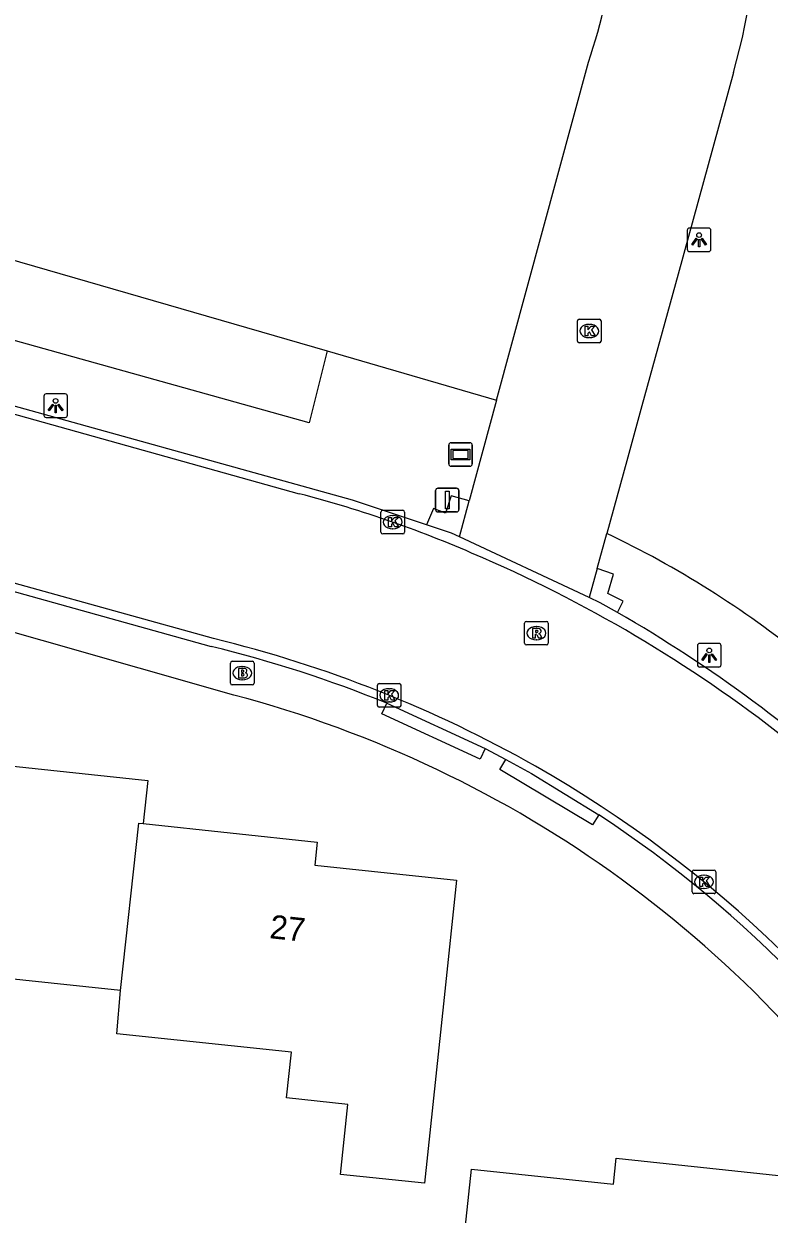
# Model space of a CAD drawing. Extents: x 162157 to 163165, y 378998 to 380775.
# Drawn here: x 162604.1 to 162635.7, y 380579.8 to 380630.1 of the extents above; entities that cross this region are included whole.
import ezdxf

# ---------------------------------------------------------------- set-up
doc = ezdxf.new("R2010")
doc.units = 0
for name, color, linetype in [('IMGEO_Afsluitpaal', 7, 'Continuous'), ('IMGEO_Berm_groen', 7, 'Continuous'), ('IMGEO_Brandkraan', 7, 'Continuous'), ('IMGEO_Groenvoorziening', 7, 'Continuous'), ('IMGEO_Kolk', 7, 'Continuous'), ('IMGEO_Lichtpunt', 7, 'Continuous'), ('IMGEO_Pand', 7, 'Continuous'), ('IMGEO_Pand_nummerreeks', 7, 'Continuous'), ('IMGEO_Rijbaan_lokaal_gesloten', 7, 'Continuous'), ('IMGEO_Rijbaan_lokaal_open', 7, 'Continuous'), ('IMGEO_Rioolput', 7, 'Continuous'), ('IMGEO_Verklikker', 7, 'Continuous'), ('IMGEO_Voetpad_open', 7, 'Continuous')]:
    doc.layers.add(name, color=color, linetype=linetype)

msp = doc.modelspace()

# ---------------------------------------------------------------- linework, layer by layer
at = {"layer": 'IMGEO_Afsluitpaal'}
for p, q in [((162621.56, 380609.58), (162621.56, 380610.38)), ((162621.56, 380610.38), (162621.56, 380609.58)), ((162621.66, 380610.48), (162622.45, 380610.48)), ((162622.45, 380610.48), (162621.66, 380610.48)), ((162622.55, 380610.38), (162622.55, 380609.58)), ((162622.55, 380609.58), (162622.55, 380610.38)), ((162622.45, 380609.48), (162621.66, 380609.48)), ((162621.66, 380609.48), (162622.45, 380609.48))]:
    msp.add_line(p, q, dxfattribs=at)
msp.add_lwpolyline([(162621.98, 380610.355), (162622.13, 380610.355), (162622.13, 380609.605), (162621.98, 380609.605), (162621.98, 380610.355)], dxfattribs=at)
for centre, start, end in [((162621.66, 380610.38), 90, 180), ((162621.66, 380610.38), 90, 180), ((162622.45, 380610.38), 0, 90), ((162622.45, 380610.38), 360, 90), ((162621.66, 380609.58), 180, 270), ((162621.66, 380609.58), 180, 270), ((162622.45, 380609.58), 270, 0), ((162622.45, 380609.58), 270, 0)]:
    msp.add_arc(centre, 0.1, start, end, dxfattribs=at)
at = {"layer": 'IMGEO_Berm_groen'}
for points in [[(162616.972, 380616.299), (162616.207, 380613.255), (162569.302, 380626.35)], [(162616.972, 380616.299), (162624.141, 380614.215)]]:
    msp.add_lwpolyline(points, dxfattribs=at)
msp.add_arc((162610.535, 380570.327), 42.385, 51.0619, 64.4657, dxfattribs=at)
at = {"layer": 'IMGEO_Brandkraan'}
for p, q in [((162612.951, 380603.158), (162613.803, 380603.158)), ((162612.876, 380602.232), (162612.876, 380603.084)), ((162613.364, 380602.938), (162613.389, 380602.938)), ((162613.877, 380603.084), (162613.877, 380602.232)), ((162613.803, 380602.158), (162612.951, 380602.158)), ((162613.387, 380602.378), (162613.362, 380602.378))]:
    msp.add_line(p, q, dxfattribs=at)
for points in [[(162612.951, 380603.158), (162613.803, 380603.158)], [(162612.876, 380602.232), (162612.876, 380603.084)], [(162613.224, 380602.858), (162613.224, 380602.458), (162613.437, 380602.458)], [(162613.455, 380602.858), (162613.224, 380602.858)], [(162613.403, 380602.777), (162613.349, 380602.777), (162613.349, 380602.701)], [(162613.349, 380602.701), (162613.402, 380602.701)], [(162613.877, 380603.084), (162613.877, 380602.232)], [(162613.803, 380602.158), (162612.951, 380602.158)], [(162613.411, 380602.625), (162613.349, 380602.625), (162613.349, 380602.544)], [(162613.349, 380602.544), (162613.411, 380602.544)]]:
    msp.add_lwpolyline(points, dxfattribs=at)
for centre, radius, start, end in [((162612.953, 380603.082), 0.0765, 91.552, 178.448), ((162612.953, 380603.082), 0.0765, 91.552, 178.448), ((162613.801, 380603.082), 0.0765, 1.552, 88.448), ((162613.801, 380603.082), 0.0765, 1.552, 88.448), ((162613.404, 380602.739), 0.0379, 267.8285, 90.9355), ((162613.459, 380602.713), 0.145, 59.4692, 91.5367), ((162613.484, 380602.76), 0.0922, 285.5137, 58.1501), ((162613.489, 380602.568), 0.105, 301.3115, 78.989), ((162612.953, 380602.234), 0.0765, 181.552, 268.448), ((162612.953, 380602.234), 0.0765, 181.552, 268.448), ((162613.412, 380602.584), 0.0404, 269.8759, 90.5077), ((162613.443, 380602.709), 0.251, 268.6676, 293.5347), ((162613.801, 380602.234), 0.0765, 271.552, 358.448), ((162613.801, 380602.234), 0.0765, 271.552, 358.448)]:
    msp.add_arc(centre, radius, start, end, dxfattribs=at)
for centre, major_axis, ratio, start_param, end_param in [((162613.363, 380602.658), (-0.387, 0.002), 0.722429, 4.712389, 7.853982), ((162613.388, 380602.658), (-0.39, 0.002), 0.717154, 1.570796, 4.712389)]:
    msp.add_ellipse(centre, major_axis=major_axis, ratio=ratio, start_param=start_param, end_param=end_param, dxfattribs=at)
at = {"layer": 'IMGEO_Groenvoorziening'}
msp.add_lwpolyline([(162569.302, 380626.35), (162569.74, 380629.441), (162587.591, 380624.791), (162616.972, 380616.299)], dxfattribs=at)
at = {"layer": 'IMGEO_Kolk'}
for p, q in [((162627.566, 380616.712), (162627.566, 380617.564)), ((162627.641, 380617.638), (162628.493, 380617.638)), ((162628.054, 380617.418), (162628.079, 380617.418)), ((162628.567, 380617.564), (162628.567, 380616.712)), ((162628.077, 380616.858), (162628.052, 380616.858)), ((162628.493, 380616.638), (162627.641, 380616.638)), ((162619.246, 380608.622), (162619.246, 380609.474)), ((162619.321, 380609.548), (162620.173, 380609.548)), ((162619.734, 380609.328), (162619.759, 380609.328)), ((162620.247, 380609.474), (162620.247, 380608.622)), ((162619.757, 380608.768), (162619.732, 380608.768)), ((162620.173, 380608.548), (162619.321, 380608.548)), ((162619.095, 380601.29), (162619.095, 380602.142)), ((162619.17, 380602.216), (162620.022, 380602.216)), ((162620.096, 380602.142), (162620.096, 380601.29)), ((162619.583, 380601.996), (162619.608, 380601.996)), ((162620.022, 380601.216), (162619.17, 380601.216)), ((162619.606, 380601.436), (162619.581, 380601.436)), ((162632.422, 380593.394), (162632.422, 380594.246)), ((162632.497, 380594.32), (162633.349, 380594.32)), ((162632.91, 380594.1), (162632.935, 380594.1)), ((162633.423, 380594.246), (162633.423, 380593.394)), ((162633.349, 380593.32), (162632.497, 380593.32)), ((162632.933, 380593.54), (162632.908, 380593.54))]:
    msp.add_line(p, q, dxfattribs=at)
for points in [[(162627.566, 380616.712), (162627.566, 380617.564)], [(162627.641, 380617.638), (162628.493, 380617.638)], [(162627.887, 380617.338), (162628.01, 380617.338), (162628.01, 380617.187), (162628.14, 380617.338), (162628.304, 380617.338), (162628.158, 380617.187), (162628.311, 380616.938), (162628.159, 380616.938), (162628.074, 380617.102), (162628.01, 380617.035), (162628.01, 380616.938), (162627.887, 380616.938), (162627.887, 380617.338)], [(162628.567, 380617.564), (162628.567, 380616.712)], [(162628.493, 380616.638), (162627.641, 380616.638)], [(162619.246, 380608.622), (162619.246, 380609.474)], [(162619.321, 380609.548), (162620.173, 380609.548)], [(162619.567, 380609.248), (162619.69, 380609.248), (162619.69, 380609.097), (162619.82, 380609.248), (162619.984, 380609.248), (162619.838, 380609.097), (162619.991, 380608.848), (162619.839, 380608.848), (162619.754, 380609.012), (162619.69, 380608.945), (162619.69, 380608.848), (162619.567, 380608.848), (162619.567, 380609.248)], [(162620.247, 380609.474), (162620.247, 380608.622)], [(162620.173, 380608.548), (162619.321, 380608.548)], [(162619.095, 380601.29), (162619.095, 380602.142)], [(162619.17, 380602.216), (162620.022, 380602.216)], [(162620.096, 380602.142), (162620.096, 380601.29)], [(162619.416, 380601.916), (162619.539, 380601.916), (162619.539, 380601.765), (162619.669, 380601.916), (162619.833, 380601.916), (162619.687, 380601.765), (162619.84, 380601.516), (162619.688, 380601.516), (162619.603, 380601.68), (162619.539, 380601.613), (162619.539, 380601.516), (162619.416, 380601.516), (162619.416, 380601.916)], [(162620.022, 380601.216), (162619.17, 380601.216)], [(162632.422, 380593.394), (162632.422, 380594.246)], [(162632.497, 380594.32), (162633.349, 380594.32)], [(162633.423, 380594.246), (162633.423, 380593.394)], [(162632.743, 380594.02), (162632.866, 380594.02), (162632.866, 380593.869), (162632.996, 380594.02), (162633.16, 380594.02), (162633.014, 380593.869), (162633.167, 380593.62), (162633.015, 380593.62), (162632.93, 380593.784), (162632.866, 380593.717), (162632.866, 380593.62), (162632.743, 380593.62), (162632.743, 380594.02)], [(162633.349, 380593.32), (162632.497, 380593.32)]]:
    msp.add_lwpolyline(points, dxfattribs=at)
for centre, start, end in [((162627.643, 380617.562), 91.552, 178.448), ((162627.643, 380617.562), 91.552, 178.448), ((162628.491, 380617.562), 1.552, 88.448), ((162628.491, 380617.562), 1.552, 88.448), ((162627.643, 380616.714), 181.552, 268.448), ((162627.643, 380616.714), 181.552, 268.448), ((162628.491, 380616.714), 271.552, 358.448), ((162628.491, 380616.714), 271.552, 358.448), ((162619.323, 380609.472), 91.552, 178.448), ((162619.323, 380609.472), 91.552, 178.448), ((162620.171, 380609.472), 1.552, 88.448), ((162620.171, 380609.472), 1.552, 88.448), ((162619.323, 380608.624), 181.552, 268.448), ((162619.323, 380608.624), 181.552, 268.448), ((162620.171, 380608.624), 271.552, 358.448), ((162620.171, 380608.624), 271.552, 358.448), ((162619.172, 380602.14), 91.552, 178.448), ((162619.172, 380602.14), 91.552, 178.448), ((162620.02, 380602.14), 1.552, 88.448), ((162620.02, 380602.14), 1.552, 88.448), ((162619.172, 380601.292), 181.552, 268.448), ((162619.172, 380601.292), 181.552, 268.448), ((162620.02, 380601.292), 271.552, 358.448), ((162620.02, 380601.292), 271.552, 358.448), ((162632.499, 380594.244), 91.552, 178.448), ((162632.499, 380594.244), 91.552, 178.448), ((162633.347, 380594.244), 1.552, 88.448), ((162633.347, 380594.244), 1.552, 88.448), ((162632.499, 380593.396), 181.552, 268.448), ((162632.499, 380593.396), 181.552, 268.448), ((162633.347, 380593.396), 271.552, 358.448), ((162633.347, 380593.396), 271.552, 358.448)]:
    msp.add_arc(centre, 0.0765, start, end, dxfattribs=at)
for centre, major_axis, ratio, start_param, end_param in [((162628.053, 380617.138), (-0.387, 0.002), 0.722429, 4.712389, 7.853982), ((162628.078, 380617.138), (-0.39, 0.002), 0.717154, 1.570796, 4.712389), ((162619.733, 380609.048), (-0.387, 0.002), 0.722429, 4.712389, 7.853982), ((162619.758, 380609.048), (-0.39, 0.002), 0.717154, 1.570796, 4.712389), ((162619.582, 380601.716), (-0.387, 0.002), 0.722429, 4.712389, 7.853982), ((162619.607, 380601.716), (-0.39, 0.002), 0.717154, 1.570796, 4.712389), ((162632.909, 380593.82), (-0.387, 0.002), 0.722429, 4.712389, 7.853982), ((162632.934, 380593.82), (-0.39, 0.002), 0.717154, 1.570796, 4.712389)]:
    msp.add_ellipse(centre, major_axis=major_axis, ratio=ratio, start_param=start_param, end_param=end_param, dxfattribs=at)
at = {"layer": 'IMGEO_Lichtpunt'}
for p, q in [((162632.217, 380621.402), (162632.217, 380620.595)), ((162632.217, 380621.402), (162632.217, 380620.595)), ((162633.119, 380621.497), (162632.311, 380621.497)), ((162633.119, 380621.497), (162632.311, 380621.497)), ((162633.213, 380620.595), (162633.213, 380621.402)), ((162633.213, 380620.595), (162633.213, 380621.402)), ((162632.311, 380620.501), (162633.119, 380620.501)), ((162632.311, 380620.501), (162633.119, 380620.501)), ((162604.977, 380614.383), (162604.977, 380613.576)), ((162604.977, 380614.383), (162604.977, 380613.576)), ((162605.879, 380614.478), (162605.071, 380614.478)), ((162605.879, 380614.478), (162605.071, 380614.478)), ((162605.973, 380613.576), (162605.973, 380614.383)), ((162605.973, 380613.576), (162605.973, 380614.383)), ((162605.071, 380613.482), (162605.879, 380613.482)), ((162605.071, 380613.482), (162605.879, 380613.482)), ((162632.647, 380603.816), (162632.647, 380603.009)), ((162632.647, 380603.816), (162632.647, 380603.009)), ((162633.549, 380603.911), (162632.741, 380603.911)), ((162633.549, 380603.911), (162632.741, 380603.911)), ((162633.643, 380603.009), (162633.643, 380603.816)), ((162633.643, 380603.009), (162633.643, 380603.816)), ((162632.741, 380602.915), (162633.549, 380602.915)), ((162632.741, 380602.915), (162633.549, 380602.915))]:
    msp.add_line(p, q, dxfattribs=at)
for points in [[(162632.591, 380621.066), (162632.63, 380621.038), (162632.442, 380620.776), (162632.404, 380620.803), (162632.591, 380621.066)], [(162632.693, 380621.018), (162632.74, 380621.018), (162632.74, 380620.696), (162632.693, 380620.696), (162632.693, 380621.018)], [(162632.803, 380621.038), (162632.841, 380621.065), (162633.028, 380620.803), (162632.989, 380620.775), (162632.803, 380621.038)], [(162605.351, 380614.047), (162605.39, 380614.019), (162605.202, 380613.757), (162605.164, 380613.784), (162605.351, 380614.047)], [(162605.453, 380613.999), (162605.5, 380613.999), (162605.5, 380613.677), (162605.453, 380613.677), (162605.453, 380613.999)], [(162605.563, 380614.019), (162605.601, 380614.046), (162605.788, 380613.784), (162605.749, 380613.756), (162605.563, 380614.019)], [(162633.021, 380603.48), (162633.06, 380603.452), (162632.872, 380603.19), (162632.834, 380603.217), (162633.021, 380603.48)], [(162633.123, 380603.432), (162633.17, 380603.432), (162633.17, 380603.11), (162633.123, 380603.11), (162633.123, 380603.432)], [(162633.233, 380603.452), (162633.271, 380603.479), (162633.458, 380603.217), (162633.419, 380603.189), (162633.233, 380603.452)]]:
    msp.add_lwpolyline(points, dxfattribs=at)
for centre in [(162632.716, 380621.2), (162605.476, 380614.181), (162633.146, 380603.614)]:
    msp.add_circle(centre, 0.0994, dxfattribs=at)
for centre, start, end in [((162632.311, 380621.402), 90, 180), ((162632.311, 380621.402), 90, 180), ((162633.119, 380621.402), 0, 90), ((162633.119, 380621.402), 0, 90), ((162632.311, 380620.595), 180, 270), ((162632.311, 380620.595), 180, 270), ((162633.119, 380620.595), 270, 0), ((162633.119, 380620.595), 270, 360), ((162605.071, 380614.383), 90, 180), ((162605.071, 380614.383), 90, 180), ((162605.879, 380614.383), 0, 90), ((162605.879, 380614.383), 0, 90), ((162605.071, 380613.576), 180, 270), ((162605.071, 380613.576), 180, 270), ((162605.879, 380613.576), 270, 0), ((162605.879, 380613.576), 270, 360), ((162632.741, 380603.816), 90, 180), ((162632.741, 380603.816), 90, 180), ((162633.549, 380603.816), 0, 90), ((162633.549, 380603.816), 0, 90), ((162632.741, 380603.009), 180, 270), ((162632.741, 380603.009), 180, 270), ((162633.549, 380603.009), 270, 0), ((162633.549, 380603.009), 270, 360)]:
    msp.add_arc(centre, 0.0946, start, end, dxfattribs=at)
at = {"layer": 'IMGEO_Pand'}
for points in [[(162608.217, 380589.225), (162601.141, 380589.975), (162600.937, 380588.052), (162594.703, 380588.713), (162595.216, 380593.557), (162595.743, 380598.529), (162601.706, 380597.897), (162601.813, 380598.913), (162609.379, 380598.111), (162609.185, 380596.286)], [(162609.185, 380596.286), (162616.55, 380595.505), (162616.447, 380594.531), (162622.452, 380593.894), (162621.925, 380588.922), (162621.092, 380581.061), (162617.531, 380581.439), (162617.845, 380584.4), (162615.255, 380584.674), (162615.46, 380586.605), (162608.071, 380587.388), (162608.217, 380589.225)], [(162608.217, 380589.225), (162609.004, 380596.305), (162609.185, 380596.286)], [(162623.079, 380581.654), (162629.092, 380581.017), (162629.208, 380582.117), (162636.747, 380581.318), (162635.782, 380572.214), (162628.507, 380572.985), (162628.304, 380571.067), (162622.027, 380571.733), (162623.079, 380581.654)]]:
    msp.add_lwpolyline(points, dxfattribs=at)
at = {"layer": 'IMGEO_Rijbaan_lokaal_gesloten'}
for points in [[(162495.123, 380643.816), (162500, 380642.467), (162522.294, 380636.301), (162522.653, 380636.202), (162528.458, 380634.586), (162577.262, 380621.022), (162615.787, 380610.248)], [(162612.155, 380604.118), (162600.248, 380607.426)], [(162600.159, 380607.105), (162612.062, 380603.781)], [(162619.494, 380601.38), (162623.661, 380599.466)], [(162623.661, 380599.466), (162624.537, 380599.006)], [(162624.537, 380599.006), (162625.614, 380598.411), (162628.466, 380596.663)]]:
    msp.add_lwpolyline(points, dxfattribs=at)
for centre, radius, start, end in [((162603.426, 380562.398), 49.421, 65.9596, 75.5154), ((162600.336, 380554.092), 58.268, 36.18143, 66.51187), ((162599.704, 380552.826), 52.432, 67.825, 76.3676), ((162599.697, 380552.786), 52.822, 60.4007, 76.3578), ((162600.412, 380554.071), 51.351, 31.3235, 60.387), ((162600.349, 380554.01), 51.087, 31.347, 56.6074)]:
    msp.add_arc(centre, radius, start, end, dxfattribs=at)
at = {"layer": 'IMGEO_Rijbaan_lokaal_open'}
for points in [[(162624.141, 380614.215), (162628.027, 380628.511)], [(162634.171, 380628.076), (162631.823, 380619.542), (162630.29, 380613.969), (162629.651, 380611.647), (162628.805, 380608.572)], [(162621.173, 380608.939), (162618.039, 380609.977), (162569.3, 380623.525)], [(162624.141, 380614.215), (162622.982, 380609.951)], [(162622.982, 380609.951), (162622.224, 380610.156), (162621.983, 380609.429), (162621.474, 380609.619), (162621.173, 380608.939)], [(162622.569, 380608.431), (162622.982, 380609.951)], [(162622.569, 380608.431), (162622.236, 380608.587), (162621.173, 380608.939)], [(162628.058, 380605.859), (162622.569, 380608.431)], [(162628.396, 380607.088), (162628.805, 380608.572)], [(162628.396, 380607.088), (162628.058, 380605.859)], [(162629.264, 380605.221), (162629.495, 380605.695), (162628.849, 380606.031), (162629.096, 380606.85), (162628.396, 380607.088)], [(162629.264, 380605.221), (162628.533, 380605.636), (162628.058, 380605.859)]]:
    msp.add_lwpolyline(points, dxfattribs=at)
for centre, radius, start, end in [((162607.542, 380635.604), 21.678, 340.9014, 9.1731), ((162607.107, 380635.702), 28.118, 344.2637, 0.9479), ((162598.916, 380552.638), 60.712, 47.06893, 60.00871)]:
    msp.add_arc(centre, radius, start, end, dxfattribs=at)
at = {"layer": 'IMGEO_Rioolput'}
for p, q in [((162625.33, 380603.921), (162625.33, 380604.773)), ((162625.405, 380604.847), (162626.257, 380604.847)), ((162626.331, 380604.773), (162626.331, 380603.921)), ((162625.818, 380604.627), (162625.843, 380604.627)), ((162626.257, 380603.847), (162625.405, 380603.847)), ((162625.841, 380604.067), (162625.816, 380604.067))]:
    msp.add_line(p, q, dxfattribs=at)
for points in [[(162625.33, 380603.921), (162625.33, 380604.773)], [(162625.405, 380604.847), (162626.257, 380604.847)], [(162626.331, 380604.773), (162626.331, 380603.921)], [(162625.919, 380604.545), (162625.667, 380604.547), (162625.667, 380604.147)], [(162625.667, 380604.147), (162625.791, 380604.147), (162625.791, 380604.309), (162625.802, 380604.309)], [(162625.845, 380604.466), (162625.791, 380604.466), (162625.791, 380604.385)], [(162625.791, 380604.385), (162625.843, 380604.385)], [(162625.849, 380604.28), (162625.92, 380604.147), (162626.06, 380604.147), (162625.995, 380604.273)], [(162626.257, 380603.847), (162625.405, 380603.847)]]:
    msp.add_lwpolyline(points, dxfattribs=at)
for centre, radius, start, end in [((162625.407, 380604.771), 0.0765, 91.552, 178.448), ((162625.407, 380604.771), 0.0765, 91.552, 178.448), ((162626.255, 380604.771), 0.0765, 1.552, 88.448), ((162626.255, 380604.771), 0.0765, 1.552, 88.448), ((162625.801, 380604.256), 0.0533, 26.0293, 88.6989), ((162625.827, 380604.574), 0.19, 274.7715, 282.9687), ((162625.851, 380604.37), 0.0964, 77.0061, 93.1865), ((162625.865, 380604.427), 0.0378, 276.6634, 79.6772), ((162625.918, 380604.435), 0.109, 350.3612, 89.416), ((162625.916, 380604.435), 0.112, 277.5842, 350.9817), ((162625.9, 380604.22), 0.108, 29.5134, 73.7905), ((162625.407, 380603.923), 0.0765, 181.552, 268.448), ((162625.407, 380603.923), 0.0765, 181.552, 268.448), ((162626.255, 380603.923), 0.0765, 271.552, 358.448), ((162626.255, 380603.923), 0.0765, 271.552, 358.448)]:
    msp.add_arc(centre, radius, start, end, dxfattribs=at)
for centre, major_axis, ratio, start_param, end_param in [((162625.817, 380604.347), (-0.387, 0.002), 0.722429, 4.712389, 7.853982), ((162625.842, 380604.347), (-0.39, 0.002), 0.717154, 1.570796, 4.712389)]:
    msp.add_ellipse(centre, major_axis=major_axis, ratio=ratio, start_param=start_param, end_param=end_param, dxfattribs=at)
at = {"layer": 'IMGEO_Verklikker'}
for p, q in [((162622.12, 380611.51), (162622.12, 380612.31)), ((162622.12, 380612.31), (162622.12, 380611.51)), ((162622.22, 380612.41), (162623.01, 380612.41)), ((162623.01, 380612.41), (162622.22, 380612.41)), ((162623.11, 380612.31), (162623.11, 380611.51)), ((162623.11, 380611.51), (162623.11, 380612.31)), ((162623.01, 380611.41), (162622.22, 380611.41)), ((162622.22, 380611.41), (162623.01, 380611.41))]:
    msp.add_line(p, q, dxfattribs=at)
for points in [[(162622.221, 380612.142), (162623.009, 380612.142), (162623.009, 380611.678), (162622.221, 380611.678), (162622.221, 380612.142)], [(162622.286, 380612.077), (162622.286, 380611.743), (162622.944, 380611.743), (162622.944, 380612.077), (162622.286, 380612.077)]]:
    msp.add_lwpolyline(points, dxfattribs=at)
for centre, start, end in [((162622.22, 380612.31), 90, 180), ((162622.22, 380612.31), 90, 180), ((162623.01, 380612.31), 0, 90), ((162623.01, 380612.31), 360, 90), ((162622.22, 380611.51), 180, 270), ((162622.22, 380611.51), 180, 270), ((162623.01, 380611.51), 270, 0), ((162623.01, 380611.51), 270, 0)]:
    msp.add_arc(centre, 0.1, start, end, dxfattribs=at)
at = {"layer": 'IMGEO_Voetpad_open'}
for points in [[(162613.014, 380601.728), (162588.761, 380608.641), (162562.907, 380615.723), (162561.588, 380616.076)], [(162623.661, 380599.466), (162623.453, 380599.012), (162619.285, 380600.926), (162619.494, 380601.38)], [(162628.466, 380596.663), (162628.21, 380596.234), (162624.281, 380598.577), (162624.537, 380599.006)]]:
    msp.add_lwpolyline(points, dxfattribs=at)
msp.add_arc((162600.441, 380554.108), 49.251, 32.7166, 75.2098, dxfattribs=at)

# ---------------------------------------------------------------- texts
at = {"layer": 'IMGEO_Pand_nummerreeks'}
msp.add_text('27', height=1, rotation=353.9448, dxfattribs=at).set_placement((162614.507, 380591.438))

doc.saveas('drawing.dxf')
